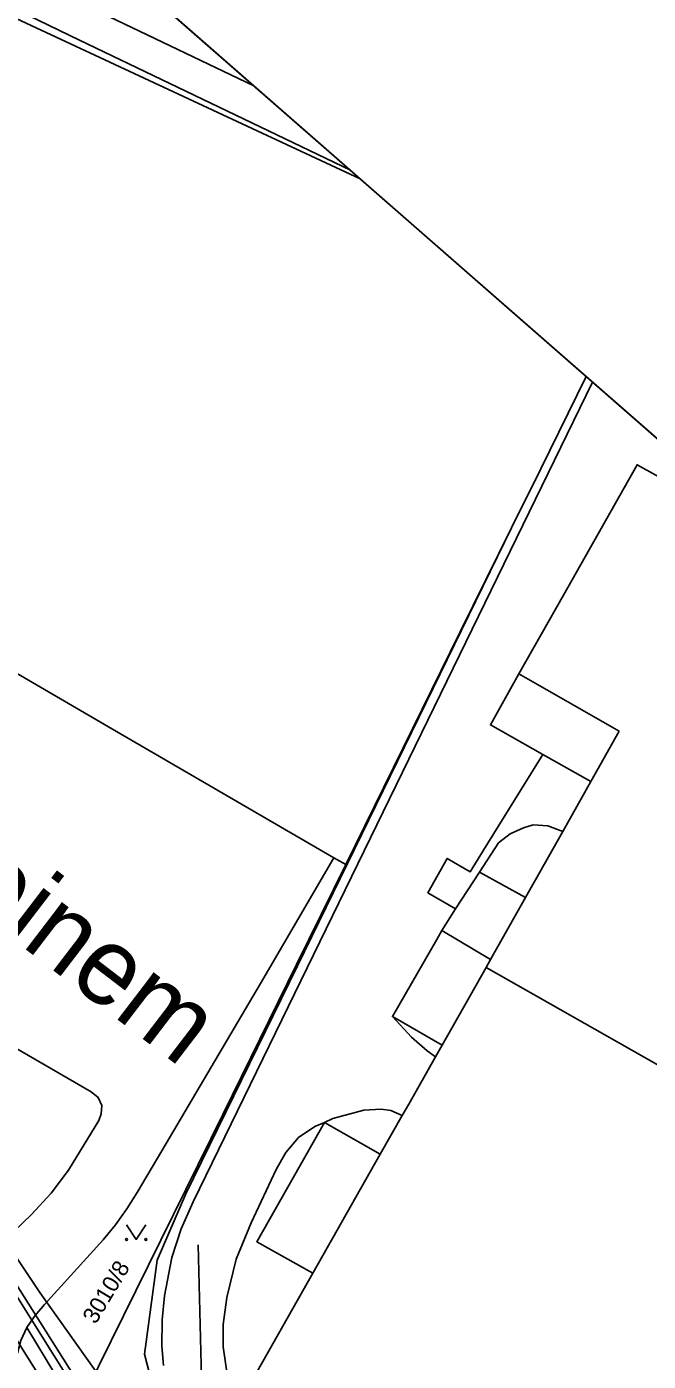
# Model space of a CAD drawing. Extents: x -620475 to -619963, y -1123010 to -1122510.
# Drawn here: x -620172.3 to -620108.2, y -1122755.4 to -1122617.9 of the extents above; entities that cross this region are included whole.
import ezdxf

# ---------------------------------------------------------------- set-up
doc = ezdxf.new("R2010")
doc.units = 0
for name, color, linetype in [('CETIN', 7, 'Continuous'), ('Hranice parcel', 7, 'Continuous'), ('Parcelní čísla', 7, 'Continuous'), ('Rámečky', 7, 'Continuous'), ('Rámečky-tisk', 7, 'Continuous'), ('VAS stoka', 7, 'Continuous'), ('VAS vodovod', 7, 'Continuous'), ('Vnitřní kresba', 7, 'Continuous'), ('Vrstva 23', 7, 'Continuous'), ('Značky kultur', 7, 'Continuous')]:
    doc.layers.add(name, color=color, linetype=linetype)

msp = doc.modelspace()

# ---------------------------------------------------------------- linework, layer by layer
at = {"layer": 'CETIN'}
for points in [[(-620322.39, -1122622.26), (-620301.06, -1122636.75), (-620273.54, -1122652.22), (-620253.25, -1122663.16), (-620204.02, -1122698.84), (-620159.64, -1122769.19), (-620144.67, -1122791.29), (-620140.33, -1122798.33), (-620134.98, -1122805.25), (-620121.23, -1122817.18), (-620095.95, -1122832.42), (-620068, -1122848.18)], [(-620277.38, -1122640.15), (-620276.74, -1122645.99), (-620273.83, -1122650.1), (-620271.73, -1122651.88), (-620253.98, -1122661.12), (-620237.57, -1122672.68), (-620221.58, -1122684.68), (-620204.03, -1122697.14), (-620190.46, -1122716.45), (-620176.22, -1122740.39), (-620170.94, -1122748.28)], [(-620170.94, -1122748.28), (-620164.26, -1122757.63)], [(-620164.26, -1122757.63), (-620170.94, -1122748.28)]]:
    msp.add_lwpolyline(points, dxfattribs=at)
at = {"layer": 'Hranice parcel'}
for p, q in [((-620252.8, -1122580.02), (-620137.91, -1122633.55)), ((-620114.62, -1122653.92), (-620119.3, -1122663.41)), ((-620119.3, -1122663.41), (-620122.31, -1122669.51)), ((-620144.37, -1122714.62), (-620122.31, -1122669.51)), ((-620122.31, -1122669.51), (-620127.6, -1122680.22)), ((-620127.6, -1122680.22), (-620139.41, -1122704.19)), ((-620139.41, -1122704.19), (-620140.63, -1122703.48)), ((-620152.03, -1122729.88), (-620166.6, -1122759.34)), ((-620176.62, -1122743.36), (-620171.74, -1122751.13)), ((-620171.74, -1122751.13), (-620166.6, -1122759.34))]:
    msp.add_line(p, q, dxfattribs=at)
for points in [[(-620262.42, -1122632.85), (-620187.21, -1122676.39), (-620163.01, -1122690.49), (-620140.63, -1122703.48)], [(-620104.23, -1122665.87), (-620109.38, -1122663), (-620116.98, -1122676.43), (-620121.57, -1122684.55), (-620124.5, -1122689.8), (-620119.11, -1122692.84), (-620122.64, -1122698.55), (-620125.21, -1122702.71), (-620126.59, -1122704.94), (-620128.96, -1122703.55), (-620130.94, -1122707.08), (-620128.08, -1122708.75), (-620129.52, -1122710.96)], [(-620140.63, -1122703.48), (-620148.19, -1122716.42), (-620158.35, -1122733.67), (-620160.91, -1122737.97), (-620161.97, -1122739.66), (-620163.14, -1122741.3), (-620164.41, -1122742.85), (-620170.46, -1122749.51), (-620171.42, -1122750.65), (-620171.74, -1122751.13)], [(-620139.41, -1122704.19), (-620144.48, -1122714.48), (-620152.03, -1122729.88)], [(-620129.52, -1122710.96), (-620130.02, -1122711.91), (-620134.59, -1122719.84), (-620129.48, -1122722.79), (-620130.16, -1122724), (-620132.92, -1122728.86), (-620133.58, -1122730.02), (-620135.85, -1122734.02), (-620141.6, -1122730.74), (-620148.58, -1122743.04), (-620142.8, -1122746.27), (-620149.58, -1122758.23), (-620118.17, -1122776.02), (-620122.58, -1122783.75), (-620090.7, -1122801.75)], [(-620129.52, -1122710.96), (-620124.48, -1122713.98), (-620124.94, -1122714.79), (-620058.31, -1122752.59), (-620054.51, -1122754.74), (-620054.56, -1122754.84)], [(-620027.34, -1122787.19), (-620029.12, -1122790.47), (-620030.63, -1122793.23), (-620030.93, -1122793.08), (-620062.93, -1122815.9), (-620079.47, -1122827.69), (-620107.97, -1122811.15), (-620126.88, -1122800.18), (-620134.93, -1122794.41), (-620148.77, -1122775.1), (-620158.3, -1122761.8), (-620160.13, -1122754.62), (-620158.82, -1122744.94), (-620155.87, -1122738.11), (-620144.37, -1122714.62)], [(-620176.88, -1122721.09), (-620165.63, -1122727.6), (-620164.91, -1122728.17), (-620164.53, -1122728.99), (-620164.6, -1122729.87), (-620164.86, -1122730.54), (-620167.98, -1122735.66), (-620169.77, -1122738.05), (-620171.8, -1122740.25), (-620173.6, -1122742)], [(-620173.24, -1122754.52), (-620172.87, -1122753.23), (-620172.25, -1122751.89), (-620171.74, -1122751.13)]]:
    msp.add_lwpolyline(points, dxfattribs=at)
at = {"layer": 'Rámečky'}
msp.add_line((-619962.95, -1122786.6), (-620279.07, -1122510.07), dxfattribs=at)
at = {"layer": 'Rámečky-tisk'}
msp.add_lwpolyline([(-620158.49, -1123010.14), (-619962.95, -1122786.6), (-620279.07, -1122510.07)], dxfattribs=at)
at = {"layer": 'VAS stoka'}
msp.add_line((-620154.6, -1122743.36), (-620154.17, -1122760.72), dxfattribs=at)
at = {"layer": 'VAS vodovod'}
msp.add_lwpolyline([(-620187.76, -1122731.9), (-620187.61, -1122732.17), (-620187.46, -1122732.43), (-620186.51, -1122732.96), (-620185.56, -1122733.49), (-620182.4, -1122738.6), (-620179.23, -1122743.71), (-620175.45, -1122749.73), (-620171.67, -1122755.74), (-620169.77, -1122758.72), (-620167.87, -1122761.69), (-620165.51, -1122761.94), (-620163.14, -1122762.19), (-620162.67, -1122762.45), (-620162.19, -1122762.71)], dxfattribs=at)
at = {"layer": 'Vnitřní kresba'}
for p, q in [((-620223.97, -1122591.77), (-620166.84, -1122619.24)), ((-620165.34, -1122616.08), (-620148.87, -1122623.96)), ((-620166.84, -1122619.24), (-620138.93, -1122632.66)), ((-620113.99, -1122654.48), (-620155.13, -1122738.93)), ((-620111.24, -1122690.45), (-620121.57, -1122684.55)), ((-620114.16, -1122695.63), (-620111.24, -1122690.45)), ((-620119.11, -1122692.84), (-620114.16, -1122695.63)), ((-620117.05, -1122700.78), (-620114.16, -1122695.63)), ((-620122.46, -1122701.03), (-620121.09, -1122700.41)), ((-620121.09, -1122700.41), (-620120.08, -1122700.09)), ((-620120.87, -1122707.56), (-620117.05, -1122700.78)), ((-620120.08, -1122700.09), (-620118.57, -1122700.21)), ((-620118.57, -1122700.21), (-620117.05, -1122700.78)), ((-620125.62, -1122704.98), (-620123.65, -1122701.96)), ((-620123.65, -1122701.96), (-620122.46, -1122701.03)), ((-620128.08, -1122708.75), (-620125.62, -1122704.98)), ((-620125.62, -1122704.98), (-620120.87, -1122707.56)), ((-620124.48, -1122713.98), (-620120.87, -1122707.56)), ((-620124.94, -1122714.79), (-620129.48, -1122722.79)), ((-620132.63, -1122721.98), (-620134.59, -1122719.84)), ((-620131.03, -1122723.38), (-620132.63, -1122721.98)), ((-620130.16, -1122724), (-620131.03, -1122723.38)), ((-620140.72, -1122730.36), (-620137.55, -1122729.49)), ((-620137.55, -1122729.49), (-620135.75, -1122729.37)), ((-620135.75, -1122729.37), (-620134.75, -1122729.52)), ((-620134.75, -1122729.52), (-620133.58, -1122730.02)), ((-620142.59, -1122731.16), (-620141.6, -1122730.74)), ((-620141.6, -1122730.74), (-620140.72, -1122730.36)), ((-620145.58, -1122733.83), (-620144.26, -1122732.31)), ((-620144.26, -1122732.31), (-620142.59, -1122731.16)), ((-620146.56, -1122735.6), (-620145.58, -1122733.83)), ((-620142.8, -1122746.27), (-620135.85, -1122734.02)), ((-620149.15, -1122741.1), (-620146.56, -1122735.6)), ((-620156.36, -1122741.72), (-620155.13, -1122738.93)), ((-620157.32, -1122744.66), (-620156.36, -1122741.72)), ((-620150.71, -1122744.84), (-620149.15, -1122741.1)), ((-620158.07, -1122748.62), (-620157.32, -1122744.66)), ((-620151.67, -1122748.77), (-620150.71, -1122744.84)), ((-620158.33, -1122751.09), (-620158.07, -1122748.62)), ((-620152.03, -1122751.56), (-620151.67, -1122748.77)), ((-620158.37, -1122753.78), (-620158.33, -1122751.09)), ((-620152.03, -1122753.86), (-620152.03, -1122751.56)), ((-620172.25, -1122751.89), (-620165.7, -1122762.73)), ((-620158.2, -1122755.8), (-620158.37, -1122753.78)), ((-620151.58, -1122756.91), (-620152.03, -1122753.86))]:
    msp.add_line(p, q, dxfattribs=at)
at = {"layer": 'Značky kultur'}
msp.add_lwpolyline([(-620161.99, -1122741.3), (-620160.99, -1122742.8), (-620159.99, -1122741.3)], dxfattribs=at)
for centre in [(-620161.99, -1122742.8), (-620159.99, -1122742.8)]:
    msp.add_circle(centre, 0.1, dxfattribs=at)

# ---------------------------------------------------------------- texts
at = {"layer": 'Parcelní čísla'}
msp.add_text('3010/8', height=1.7, rotation=59, dxfattribs=at).set_placement((-620165.17, -1122751.62))
at = {"layer": 'Vrstva 23'}
msp.add_text('Bystřice nad Pernštejnem', height=8, rotation=322.5799, dxfattribs=at).set_placement((-620253.24, -1122651.06))

doc.saveas('drawing.dxf')
